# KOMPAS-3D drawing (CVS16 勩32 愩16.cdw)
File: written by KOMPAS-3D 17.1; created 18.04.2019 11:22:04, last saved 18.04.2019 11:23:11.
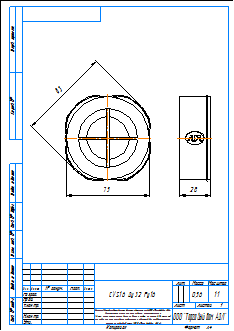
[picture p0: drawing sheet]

Sheet 1: A4, portrait

Title block, sheet 1: name: CVS16 Ду32 Ру16; material: Внимание! Данный продукт является объектом авторского права ООО «Торговый Дом АДЛ». / Запрещается изменение, копирование, распространение / (в том числе путем копирования на другие сайты и ресурсы в Интернете) / или любое иное использование информации и объектов без предварительного / согласия правообладателя (ООО «Торговый Дом АДЛ»).; mass: 0,56; sheets: 1; organisation: ООО "Торговый дом АДЛ"; sheet format: A4

Views: Вид 1, Проекционный вид 2
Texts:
  user
Dimensions and other numbers on the sheet: 83; 75; 28; 1:1; 1; 0,56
